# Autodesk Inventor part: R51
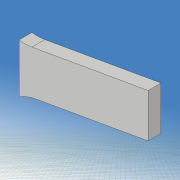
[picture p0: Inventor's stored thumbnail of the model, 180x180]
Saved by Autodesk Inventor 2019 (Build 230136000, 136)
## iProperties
Created: 2021-05
Part Number: R51
Material: 一般
Document SubType Name: Modeling
Designer: kikut
Density: 1 g/cm^3
Appearance: 既定
Mass: 0.00804985 g
Surface Area: 0.369476 cm^2
Volume: 0.00804985 cm^3
Author: kikut
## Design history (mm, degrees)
sketch "スケッチ1"
  geometry: L1 (80, 60)-(-80, 60); L2 (-80, 60)-(-80, -60); L3 (-80, -60)-(80, -60); L4 (80, -60)-(80, 60); L5 (80, 60)-(-80, -60); L6 (-80, 60)-(80, -60); 1 further point
  constraints: 12 end point, 2 midpoint, 2 parallel, 1 horizontal, 1 perpendicular
  dimensions: "d0" = 160 distance of L2.end L3.end; "d1" = 120 distance of L1.end L2.end
extrude "押し出し1" new body sketch "スケッチ1" stored distance "d2" = 0.6; taper "d3" = 0 deg
sketch "スケッチ2"
  geometry: L1 (-140, 0)-(140, 0) reference; L2 (0, -54)-(20, -30); L3 (0, 54)-(20, 30); L4 (0, -3)-(6.514, -3); L5 (6.514, -3)-(16, -6); L6 (16, -6)-(24, -3); L7 (24, -3)-(33.716, -3); L8 (0, 3)-(6.514, 3); L9 (6.514, 3)-(16, 6); L10 (16, 6)-(24, 3); L11 (24, 3)-(33.716, 3); L12 (0, -98)-(0, 98) reference; L13 (-100, -70)-(100, -70); L14 (100, -70)-(100, 70); L15 (100, 70)-(-100, 70); L16 (-100, 70)-(-100, -70); L17 (-100, -70)-(100, 70); L18 (100, -70)-(-100, 70); A1 r 60 centre (54.312, 28.5) between (0, 54) and (0, 3); A2 r 60 centre (54.312, -28.5) between (0, -3) and (0, -54); A3 r 18.111 centre (18, -12) between (20, -30) and (33.716, -3); A4 r 18.111 centre (18, 12) between (33.716, 3) and (20, 30); 1 further point
  constraints: 32 end point, 8 point on circle, 8 symmetric about line, 4 centre point, 3 horizontal, 2 collinear, 2 midpoint, 2 parallel, 1 perpendicular
  dimensions: "d5" = 60 radius of A1; "d6" = 6 distance of L8.start L4.start; "d7" = 108 distance of L3.start L2.start; "d8" = 0 horizontal distance of L3.start L8.start; "d9" = 60 distance of L3.end L2.end; "d10" = 0 horizontal distance of point (0, 0) L3.start; "d11" = 20 horizontal distance of L3.start L3.end; "d12" = 24 distance of A4.centre A3.centre; "d13" = 6 distance of L11.end L7.end; "d14" = 12 distance of L9.end L5.end; "d15" = 16 distance from line of L12 L5.end; "d16" = 24 distance from line of L6.end L12; "d17" = 200 distance of L14.end L15.end; "d18" = 140 distance of L15.end L13.start; "d30" = 18 distance from line of L12 A4.centre
extrude "押し出し2" cut sketch "スケッチ2" stored distance "d19" = 10; taper "d20" = 0 deg
sketch "スケッチ3"
  geometry: L1 (49.705, -17.97)-(33.948, -15.191); L2 (33.948, -15.191)-(34.295, -13.222); L3 (34.295, -13.222)-(50.052, -16); L4 (50.052, -16)-(49.705, -17.97); L5 (49.705, -17.97)-(34.295, -13.222); L6 (33.948, -15.191)-(50.052, -16); L7 (50.052, 16)-(34.295, 13.222); L8 (34.295, 13.222)-(33.948, 15.191); L9 (33.948, 15.191)-(49.705, 17.97); L10 (49.705, 17.97)-(50.052, 16); L11 (50.052, 16)-(33.948, 15.191); L12 (34.295, 13.222)-(49.705, 17.97); L13 (-112, 0)-(112, 0) reference; L14 (0, -84)-(0, 84) reference; 3 further points
  constraints: 24 end point, 4 midpoint, 4 parallel, 2 perpendicular, 2 symmetric about line
  dimensions: "d21" = 2 distance of L3.end L1.start; "d22" = 2 distance of L9.end L7.start; "d23" = 16 distance of L8.end L9.end; "d24" = 42 distance from line of L14 point (42, 15.596); "d26" = 10 deg angle of L7 L13; "d62" = 16 distance from line of L3.end L13
extrude "押し出し3" join sketch "スケッチ3" distance "d27" = 0.6; taper "d28" = 0 deg
fillet "フィレット1" dims "d31" = 2
fillet "フィレット2" dims "d32" = 1
sketch "スケッチ6"
  geometry: L1 (-20, 60)-(80, 60); L2 (80, 60)-(80, -60); L3 (80, -60)-(-20, -60); L4 (-20, -60)-(-20, 60); L5 (-46.168, 0)-(93.832, 0) reference; L6 (0, -84)-(0, 84) reference; L7 (37, 10)-(43, 10); L8 (43, 10)-(43, 20); L9 (43, 20)-(37, 20); L10 (37, 20)-(37, 10); 1 further point
  constraints: 16 end point, 4 parallel, 2 horizontal, 2 perpendicular, 1 other
  dimensions: "d63" = 120 distance of L3.end L1.start; "d64" = 100 distance of L1.start L1.end; "d65" = 20 distance between parallel lines of L6 L4; "d66" = 6 distance of L8.end L9.end; "d73" = 10 distance of L9.end L7.start; "d74" = 10 distance between parallel lines of L7 L5; "d75" = 57 distance between parallel lines of L10 L4
extrude "押し出し4" cut sketch "スケッチ6" stored distance "d70" = 10; taper "d71" = 0 deg
node "ソリッド1"
